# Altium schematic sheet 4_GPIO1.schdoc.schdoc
size 426 x 302 mm; Symbol: Sheet_A3_Whycan; Device: Sheet_A3; @Project Name: Avaota A1; REV: 1.0; Company: YuzukiHD; Draw By: GloomyGhost; @Update Date: 2024-02-21; @Page No: 6; @Page Count: 13
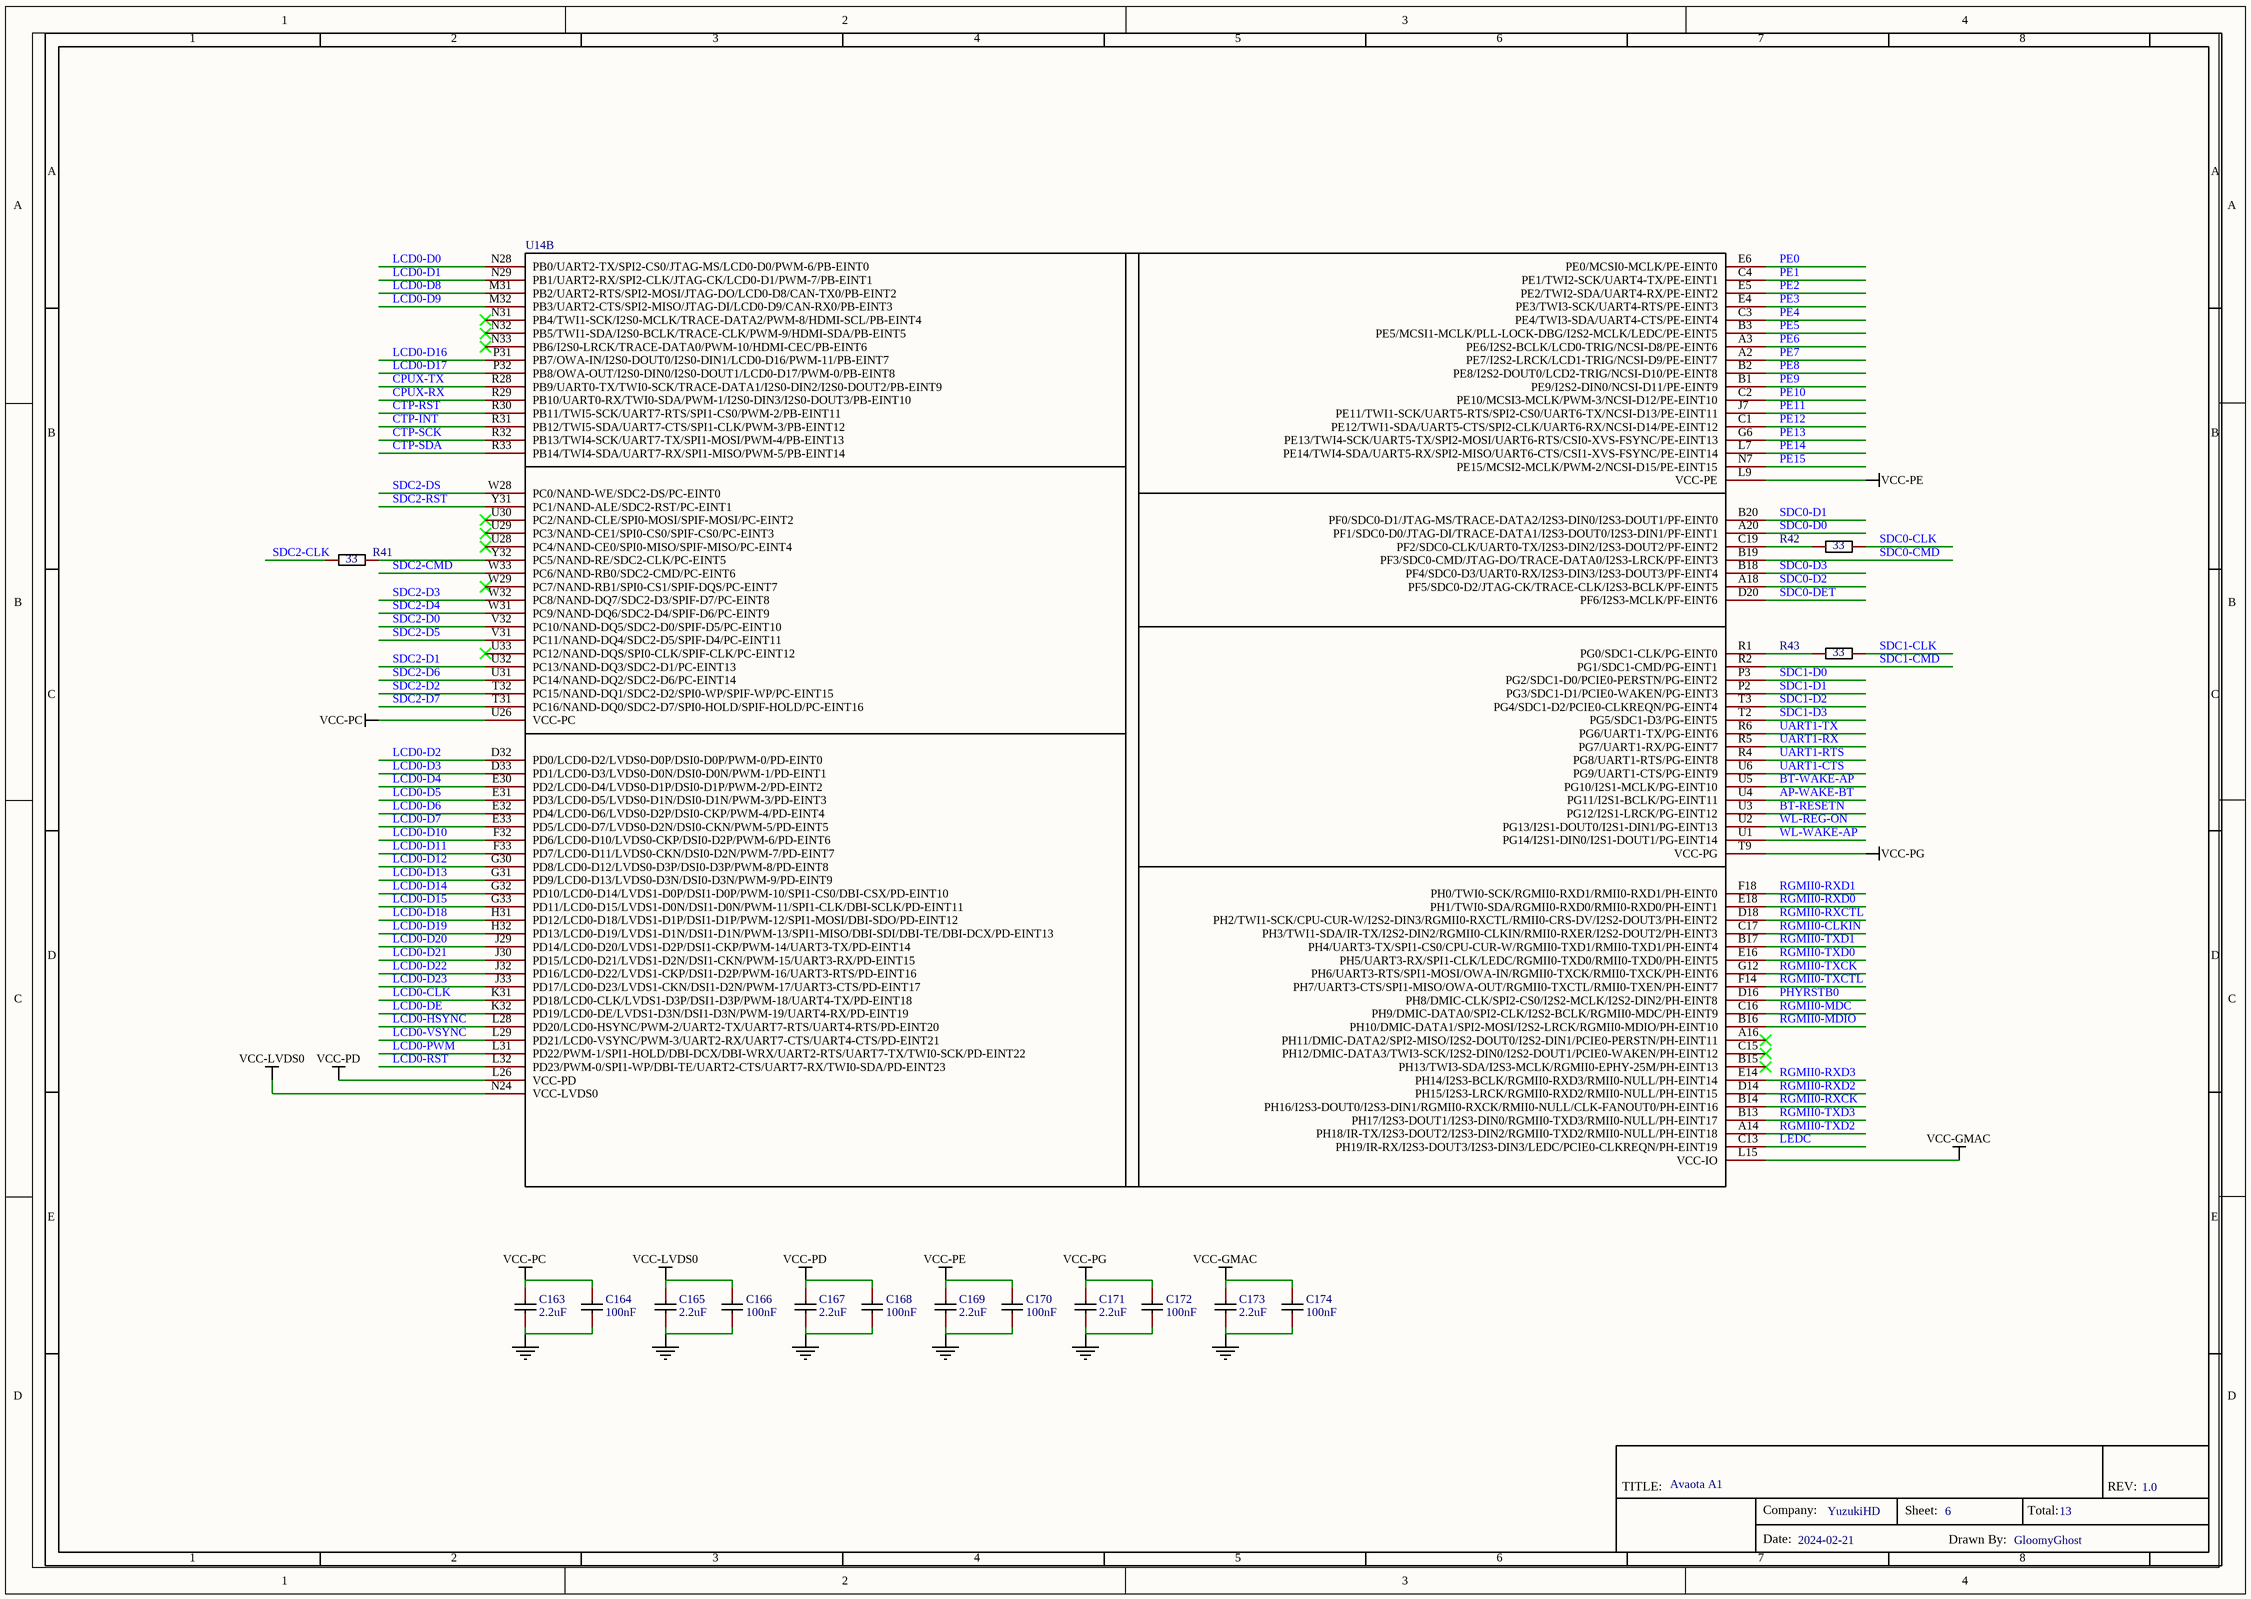
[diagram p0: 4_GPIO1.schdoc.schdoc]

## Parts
C163  2.2uF  [c0201 nsk]
C164  100nF  [c0201 nsk]
C165  2.2uF  [c0201 nsk]
C166  100nF  [c0201 nsk]
C167  2.2uF  [c0201 nsk]
C168  100nF  [c0201 nsk]
C169  2.2uF  [c0201 nsk]
C170  100nF  [c0201 nsk]
C171  2.2uF  [c0201 nsk]
C172  100nF  [c0201 nsk]
C173  2.2uF  [c0201 nsk]
C174  100nF  [c0201 nsk]
R41  33  [r0201 nsk]
R42  33  [r0201 nsk]
R43  33  [r0201 nsk]
U14  T527  [T527-BGA664]  (value not drawn)  (part B of 8)

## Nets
NetC163_1: C163.1 C164.1 C165.1 C166.1 C167.1 C168.1 C169.1 C170.1 C171.1 C172.1 C173.1 C174.1
VCC-GMAC: C173.2 C174.2 U14.L15(VCC-IO)
VCC-LVDS0: C165.2 C166.2 U14.N24(VCC-LVDS0)
VCC-PC: C163.2 C164.2 U14.U26(VCC-PC)
VCC-PD: C167.2 C168.2 U14.L26(VCC-PD)
VCC-PE: C169.2 C170.2 U14.L9(VCC-PE)
VCC-PG: C171.2 C172.2 U14.T9(VCC-PG)
AP-WAKE-BT: U14.U4(PG11/I2S1-BCLK/PG-EINT11)
BT-RESETN: U14.U3(PG12/I2S1-LRCK/PG-EINT12)
BT-WAKE-AP: U14.U5(PG10/I2S1-MCLK/PG-EINT10)
CPUX-RX: U14.R29(PB10/UART0-RX/TWI0-SDA/PWM-1/I2S0-DIN3/I2S0-DOUT3/PB-EINT10)
CPUX-TX: U14.R28(PB9/UART0-TX/TWI0-SCK/TRACE-DATA1/I2S0-DIN2/I2S0-DOUT2/PB-EINT9)
CTP-INT: U14.R31(PB12/TWI5-SDA/UART7-CTS/SPI1-CLK/PWM-3/PB-EINT12)
CTP-RST: U14.R30(PB11/TWI5-SCK/UART7-RTS/SPI1-CS0/PWM-2/PB-EINT11)
CTP-SCK: U14.R32(PB13/TWI4-SCK/UART7-TX/SPI1-MOSI/PWM-4/PB-EINT13)
CTP-SDA: U14.R33(PB14/TWI4-SDA/UART7-RX/SPI1-MISO/PWM-5/PB-EINT14)
LCD0-CLK: U14.K31(PD18/LCD0-CLK/LVDS1-D3P/DSI1-D3P/PWM-18/UART4-TX/PD-EINT18)
LCD0-D0: U14.N28(PB0/UART2-TX/SPI2-CS0/JTAG-MS/LCD0-D0/PWM-6/PB-EINT0)
LCD0-D1: U14.N29(PB1/UART2-RX/SPI2-CLK/JTAG-CK/LCD0-D1/PWM-7/PB-EINT1)
LCD0-D2: U14.D32(PD0/LCD0-D2/LVDS0-D0P/DSI0-D0P/PWM-0/PD-EINT0)
LCD0-D3: U14.D33(PD1/LCD0-D3/LVDS0-D0N/DSI0-D0N/PWM-1/PD-EINT1)
LCD0-D4: U14.E30(PD2/LCD0-D4/LVDS0-D1P/DSI0-D1P/PWM-2/PD-EINT2)
LCD0-D5: U14.E31(PD3/LCD0-D5/LVDS0-D1N/DSI0-D1N/PWM-3/PD-EINT3)
LCD0-D6: U14.E32(PD4/LCD0-D6/LVDS0-D2P/DSI0-CKP/PWM-4/PD-EINT4)
LCD0-D7: U14.E33(PD5/LCD0-D7/LVDS0-D2N/DSI0-CKN/PWM-5/PD-EINT5)
LCD0-D8: U14.M31(PB2/UART2-RTS/SPI2-MOSI/JTAG-DO/LCD0-D8/CAN-TX0/PB-EINT2)
LCD0-D9: U14.M32(PB3/UART2-CTS/SPI2-MISO/JTAG-DI/LCD0-D9/CAN-RX0/PB-EINT3)
LCD0-D10: U14.F32(PD6/LCD0-D10/LVDS0-CKP/DSI0-D2P/PWM-6/PD-EINT6)
LCD0-D11: U14.F33(PD7/LCD0-D11/LVDS0-CKN/DSI0-D2N/PWM-7/PD-EINT7)
LCD0-D12: U14.G30(PD8/LCD0-D12/LVDS0-D3P/DSI0-D3P/PWM-8/PD-EINT8)
LCD0-D13: U14.G31(PD9/LCD0-D13/LVDS0-D3N/DSI0-D3N/PWM-9/PD-EINT9)
LCD0-D14: U14.G32(PD10/LCD0-D14/LVDS1-D0P/DSI1-D0P/PWM-10/SPI1-CS0/DBI-CSX/PD-EINT10)
LCD0-D15: U14.G33(PD11/LCD0-D15/LVDS1-D0N/DSI1-D0N/PWM-11/SPI1-CLK/DBI-SCLK/PD-EINT11)
LCD0-D16: U14.P31(PB7/OWA-IN/I2S0-DOUT0/I2S0-DIN1/LCD0-D16/PWM-11/PB-EINT7)
LCD0-D17: U14.P32(PB8/OWA-OUT/I2S0-DIN0/I2S0-DOUT1/LCD0-D17/PWM-0/PB-EINT8)
LCD0-D18: U14.H31(PD12/LCD0-D18/LVDS1-D1P/DSI1-D1P/PWM-12/SPI1-MOSI/DBI-SDO/PD-EINT12)
LCD0-D19: U14.H32(PD13/LCD0-D19/LVDS1-D1N/DSI1-D1N/PWM-13/SPI1-MISO/DBI-SDI/DBI-TE/DBI-DCX/PD-EINT13)
LCD0-D20: U14.J29(PD14/LCD0-D20/LVDS1-D2P/DSI1-CKP/PWM-14/UART3-TX/PD-EINT14)
LCD0-D21: U14.J30(PD15/LCD0-D21/LVDS1-D2N/DSI1-CKN/PWM-15/UART3-RX/PD-EINT15)
LCD0-D22: U14.J32(PD16/LCD0-D22/LVDS1-CKP/DSI1-D2P/PWM-16/UART3-RTS/PD-EINT16)
LCD0-D23: U14.J33(PD17/LCD0-D23/LVDS1-CKN/DSI1-D2N/PWM-17/UART3-CTS/PD-EINT17)
LCD0-DE: U14.K32(PD19/LCD0-DE/LVDS1-D3N/DSI1-D3N/PWM-19/UART4-RX/PD-EINT19)
LCD0-HSYNC: U14.L28(PD20/LCD0-HSYNC/PWM-2/UART2-TX/UART7-RTS/UART4-RTS/PD-EINT20)
LCD0-PWM: U14.L31(PD22/PWM-1/SPI1-HOLD/DBI-DCX/DBI-WRX/UART2-RTS/UART7-TX/TWI0-SCK/PD-EINT22)
LCD0-RST: U14.L32(PD23/PWM-0/SPI1-WP/DBI-TE/UART2-CTS/UART7-RX/TWI0-SDA/PD-EINT23)
LCD0-VSYNC: U14.L29(PD21/LCD0-VSYNC/PWM-3/UART2-RX/UART7-CTS/UART4-CTS/PD-EINT21)
LEDC: U14.C13(PH19/IR-RX/I2S3-DOUT3/I2S3-DIN3/LEDC/PCIE0-CLKREQN/PH-EINT19)
PE0: U14.E6(PE0/MCSI0-MCLK/PE-EINT0)
PE1: U14.C4(PE1/TWI2-SCK/UART4-TX/PE-EINT1)
PE2: U14.E5(PE2/TWI2-SDA/UART4-RX/PE-EINT2)
PE3: U14.E4(PE3/TWI3-SCK/UART4-RTS/PE-EINT3)
PE4: U14.C3(PE4/TWI3-SDA/UART4-CTS/PE-EINT4)
PE5: U14.B3(PE5/MCSI1-MCLK/PLL-LOCK-DBG/I2S2-MCLK/LEDC/PE-EINT5)
PE6: U14.A3(PE6/I2S2-BCLK/LCD0-TRIG/NCSI-D8/PE-EINT6)
PE7: U14.A2(PE7/I2S2-LRCK/LCD1-TRIG/NCSI-D9/PE-EINT7)
PE8: U14.B2(PE8/I2S2-DOUT0/LCD2-TRIG/NCSI-D10/PE-EINT8)
PE9: U14.B1(PE9/I2S2-DIN0/NCSI-D11/PE-EINT9)
PE10: U14.C2(PE10/MCSI3-MCLK/PWM-3/NCSI-D12/PE-EINT10)
PE11: U14.J7(PE11/TWI1-SCK/UART5-RTS/SPI2-CS0/UART6-TX/NCSI-D13/PE-EINT11)
PE12: U14.C1(PE12/TWI1-SDA/UART5-CTS/SPI2-CLK/UART6-RX/NCSI-D14/PE-EINT12)
PE13: U14.G6(PE13/TWI4-SCK/UART5-TX/SPI2-MOSI/UART6-RTS/CSI0-XVS-FSYNC/PE-EINT13)
PE14: U14.L7(PE14/TWI4-SDA/UART5-RX/SPI2-MISO/UART6-CTS/CSI1-XVS-FSYNC/PE-EINT14)
PE15: U14.N7(PE15/MCSI2-MCLK/PWM-2/NCSI-D15/PE-EINT15)
PHYRSTB0: U14.D16(PH8/DMIC-CLK/SPI2-CS0/I2S2-MCLK/I2S2-DIN2/PH-EINT8)
RGMII0-CLKIN: U14.C17(PH3/TWI1-SDA/IR-TX/I2S2-DIN2/RGMII0-CLKIN/RMII0-RXER/I2S2-DOUT2/PH-EINT3)
RGMII0-MDC: U14.C16(PH9/DMIC-DATA0/SPI2-CLK/I2S2-BCLK/RGMII0-MDC/PH-EINT9)
RGMII0-MDIO: U14.B16(PH10/DMIC-DATA1/SPI2-MOSI/I2S2-LRCK/RGMII0-MDIO/PH-EINT10)
RGMII0-RXCK: U14.B14(PH16/I2S3-DOUT0/I2S3-DIN1/RGMII0-RXCK/RMII0-NULL/CLK-FANOUT0/PH-EINT16)
RGMII0-RXCTL: U14.D18(PH2/TWI1-SCK/CPU-CUR-W/I2S2-DIN3/RGMII0-RXCTL/RMII0-CRS-DV/I2S2-DOUT3/PH-EINT2)
RGMII0-RXD0: U14.E18(PH1/TWI0-SDA/RGMII0-RXD0/RMII0-RXD0/PH-EINT1)
RGMII0-RXD1: U14.F18(PH0/TWI0-SCK/RGMII0-RXD1/RMII0-RXD1/PH-EINT0)
RGMII0-RXD2: U14.D14(PH15/I2S3-LRCK/RGMII0-RXD2/RMII0-NULL/PH-EINT15)
RGMII0-RXD3: U14.E14(PH14/I2S3-BCLK/RGMII0-RXD3/RMII0-NULL/PH-EINT14)
RGMII0-TXCK: U14.G12(PH6/UART3-RTS/SPI1-MOSI/OWA-IN/RGMII0-TXCK/RMII0-TXCK/PH-EINT6)
RGMII0-TXCTL: U14.F14(PH7/UART3-CTS/SPI1-MISO/OWA-OUT/RGMII0-TXCTL/RMII0-TXEN/PH-EINT7)
RGMII0-TXD0: U14.E16(PH5/UART3-RX/SPI1-CLK/LEDC/RGMII0-TXD0/RMII0-TXD0/PH-EINT5)
RGMII0-TXD1: U14.B17(PH4/UART3-TX/SPI1-CS0/CPU-CUR-W/RGMII0-TXD1/RMII0-TXD1/PH-EINT4)
RGMII0-TXD2: U14.A14(PH18/IR-TX/I2S3-DOUT2/I2S3-DIN2/RGMII0-TXD2/RMII0-NULL/PH-EINT18)
RGMII0-TXD3: U14.B13(PH17/I2S3-DOUT1/I2S3-DIN0/RGMII0-TXD3/RMII0-NULL/PH-EINT17)
SDC0-CLK: R42.2
SDC0-CMD: U14.B19(PF3/SDC0-CMD/JTAG-DO/TRACE-DATA0/I2S3-LRCK/PF-EINT3)
SDC0-D0: U14.A20(PF1/SDC0-D0/JTAG-DI/TRACE-DATA1/I2S3-DOUT0/I2S3-DIN1/PF-EINT1)
SDC0-D1: U14.B20(PF0/SDC0-D1/JTAG-MS/TRACE-DATA2/I2S3-DIN0/I2S3-DOUT1/PF-EINT0)
SDC0-D2: U14.A18(PF5/SDC0-D2/JTAG-CK/TRACE-CLK/I2S3-BCLK/PF-EINT5)
SDC0-D3: U14.B18(PF4/SDC0-D3/UART0-RX/I2S3-DIN3/I2S3-DOUT3/PF-EINT4)
SDC0-DET: U14.D20(PF6/I2S3-MCLK/PF-EINT6)
SDC1-CLK: R43.2
SDC1-CMD: U14.R2(PG1/SDC1-CMD/PG-EINT1)
SDC1-D0: U14.P3(PG2/SDC1-D0/PCIE0-PERSTN/PG-EINT2)
SDC1-D1: U14.P2(PG3/SDC1-D1/PCIE0-WAKEN/PG-EINT3)
SDC1-D2: U14.T3(PG4/SDC1-D2/PCIE0-CLKREQN/PG-EINT4)
SDC1-D3: U14.T2(PG5/SDC1-D3/PG-EINT5)
SDC2-CLK: R41.1
SDC2-CMD: U14.W33(PC6/NAND-RB0/SDC2-CMD/PC-EINT6)
SDC2-D0: U14.V32(PC10/NAND-DQ5/SDC2-D0/SPIF-D5/PC-EINT10)
SDC2-D1: U14.U32(PC13/NAND-DQ3/SDC2-D1/PC-EINT13)
SDC2-D2: U14.T32(PC15/NAND-DQ1/SDC2-D2/SPI0-WP/SPIF-WP/PC-EINT15)
SDC2-D3: U14.W32(PC8/NAND-DQ7/SDC2-D3/SPIF-D7/PC-EINT8)
SDC2-D4: U14.W31(PC9/NAND-DQ6/SDC2-D4/SPIF-D6/PC-EINT9)
SDC2-D5: U14.V31(PC11/NAND-DQ4/SDC2-D5/SPIF-D4/PC-EINT11)
SDC2-D6: U14.U31(PC14/NAND-DQ2/SDC2-D6/PC-EINT14)
SDC2-D7: U14.T31(PC16/NAND-DQ0/SDC2-D7/SPI0-HOLD/SPIF-HOLD/PC-EINT16)
SDC2-DS: U14.W28(PC0/NAND-WE/SDC2-DS/PC-EINT0)
SDC2-RST: U14.Y31(PC1/NAND-ALE/SDC2-RST/PC-EINT1)
UART1-CTS: U14.U6(PG9/UART1-CTS/PG-EINT9)
UART1-RTS: U14.R4(PG8/UART1-RTS/PG-EINT8)
UART1-RX: U14.R5(PG7/UART1-RX/PG-EINT7)
UART1-TX: U14.R6(PG6/UART1-TX/PG-EINT6)
WL-REG-ON: U14.U2(PG13/I2S1-DOUT0/I2S1-DIN1/PG-EINT13)
WL-WAKE-AP: U14.U1(PG14/I2S1-DIN0/I2S1-DOUT1/PG-EINT14)
NetR41_2: R41.2 U14.Y32(PC5/NAND-RE/SDC2-CLK/PC-EINT5)
NetR42_1: R42.1 U14.C19(PF2/SDC0-CLK/UART0-TX/I2S3-DIN2/I2S3-DOUT2/PF-EINT2)
NetR43_1: R43.1 U14.R1(PG0/SDC1-CLK/PG-EINT0)

Not connected (* = marked no-connect by the designer): U14 A16(PH11/DMIC-DATA2/SPI2-MISO/I2S2-DOUT0/I2S2-DIN1/PCIE0-PERSTN/PH-EINT11)* B15(PH13/TWI3-SDA/I2S3-MCLK/RGMII0-EPHY-25M/PH-EINT13)* C15(PH12/DMIC-DATA3/TWI3-SCK/I2S2-DIN0/I2S2-DOUT1/PCIE0-WAKEN/PH-EINT12)* N31(PB4/TWI1-SCK/I2S0-MCLK/TRACE-DATA2/PWM-8/HDMI-SCL/PB-EINT4)* N32(PB5/TWI1-SDA/I2S0-BCLK/TRACE-CLK/PWM-9/HDMI-SDA/PB-EINT5)* N33(PB6/I2S0-LRCK/TRACE-DATA0/PWM-10/HDMI-CEC/PB-EINT6)* U28(PC4/NAND-CE0/SPI0-MISO/SPIF-MISO/PC-EINT4)* U29(PC3/NAND-CE1/SPI0-CS0/SPIF-CS0/PC-EINT3)* U30(PC2/NAND-CLE/SPI0-MOSI/SPIF-MOSI/PC-EINT2)* U33(PC12/NAND-DQS/SPI0-CLK/SPIF-CLK/PC-EINT12)* W29(PC7/NAND-RB1/SPI0-CS1/SPIF-DQS/PC-EINT7)*

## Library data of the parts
C163-C174 = GRM033R61A104KE15D: Manufacturer: muRata(村田); Add into BOM: yes; Tolerance: ±10%; Voltage Rated: 10V; Temperature Coefficient: X5R; Description: 容值:100nF;精度:±10%;额定电压:10V;材质(温度系数):X5R;
R41-R43 = Res_0201: Symbol: 电阻; Convert to PCB: yes
U14 = T527: Add into BOM: yes; SWAP_INFO: (S1+S2+S3+S4+S5+S6+S7+S8+S9); SPLIT_INST: TRUE; Description: Allwinner T527 SoC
